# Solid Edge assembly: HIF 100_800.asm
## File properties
Title: Zylinder
Author: ahadarics
Template: iso assembly.asm
Last saved by: ahadarics
Revision: 67
Application: Solid Edge
Username: ahadarics
Dokumentum tartalom típus: 1
Document Number: HIF 100/800
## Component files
Kit_2.par
Kit_1.par
Profilrohr 100_800.par
Kolbenstange 100_800.par
Mutter.par
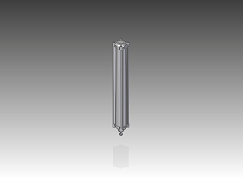
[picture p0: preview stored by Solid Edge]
